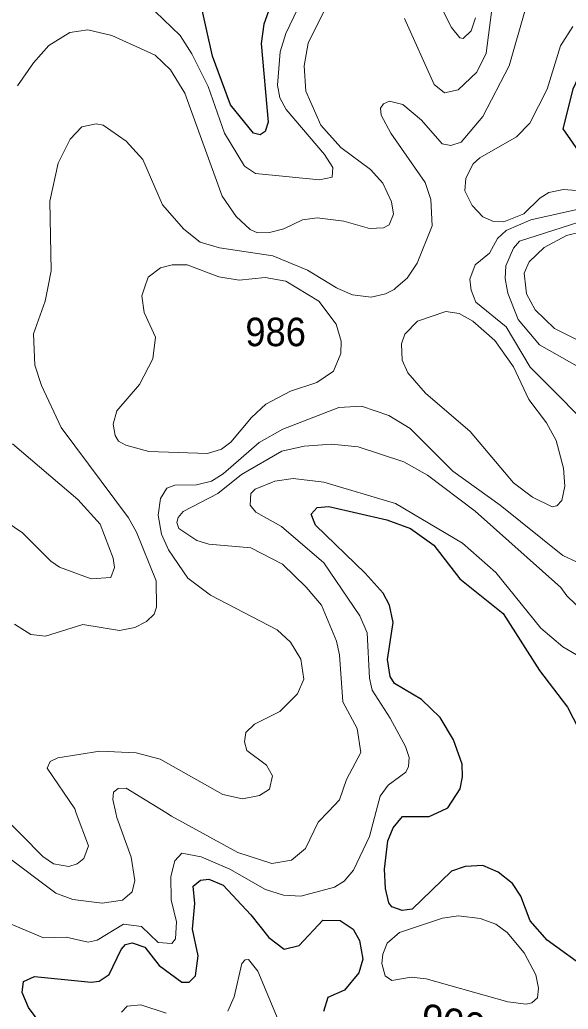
# Model space of a CAD drawing. Extents: x 473.9 to 500, y 7733.1 to 7760.8.
# Drawn here: x 478.365 to 479.903, y 7753.344 to 7756.121 of the extents above; entities that cross this region are included whole.
import ezdxf
from ezdxf.enums import TextEntityAlignment as Align

# ---------------------------------------------------------------- set-up
doc = ezdxf.new("R2010")
doc.units = 0
doc.header["$LTSCALE"] = 0.032
doc.layers.add('1', color=7, linetype='Continuous', lineweight=25)
doc.layers.add('2', color=7, linetype='Continuous', lineweight=13)
doc.layers.add('21', color=7, linetype='Continuous')
doc.layers.add('61', color=7, linetype='Continuous')

msp = doc.modelspace()

# ---------------------------------------------------------------- linework, layer by layer
at = {"layer": '1'}
for points in [[(479.0836, 7756.206), (479.0493, 7756.1087), (479.0414, 7756.0543), (479.0615, 7755.8337), (479.0529, 7755.8079), (479.0393, 7755.7982), (479.0201, 7755.8025), (478.9555, 7755.8829), (478.9053, 7756.0195), (478.8684, 7756.1871)], [(479.962, 7753.4517), (479.8435, 7753.5376), (479.7962, 7753.5923), (479.7701, 7753.6615), (479.7464, 7753.6963), (479.7067, 7753.7281), (479.6633, 7753.7472), (479.6133, 7753.7443), (479.5752, 7753.7312), (479.4652, 7753.6247), (479.4371, 7753.6212), (479.4086, 7753.6313), (479.3996, 7753.6421), (479.3903, 7753.6828), (479.3879, 7753.7371), (479.3974, 7753.8163), (479.4123, 7753.8529), (479.4382, 7753.8852), (479.513, 7753.8848), (479.5472, 7753.9005), (479.5656, 7753.9089), (479.5996, 7753.9629), (479.6064, 7753.9964), (479.6056, 7754.0315), (479.5815, 7754.1003), (479.5434, 7754.1631), (479.4915, 7754.2131), (479.4152, 7754.2582), (479.4038, 7754.2774), (479.396, 7754.3251), (479.4119, 7754.4292), (479.4014, 7754.4783), (479.3838, 7754.5116), (479.3335, 7754.5683), (479.1942, 7754.7022), (479.1822, 7754.7337), (479.1989, 7754.7518), (479.2312, 7754.7552), (479.394, 7754.7178), (479.4601, 7754.6932), (479.5258, 7754.6468), (479.5989, 7754.5524), (479.7203, 7754.4548), (479.8225, 7754.2946), (479.9008, 7754.1916), (479.9488, 7754.0995)], [(478.446, 7753.2733), (478.3895, 7753.3485), (478.3716, 7753.3909), (478.3758, 7753.4212), (478.4061, 7753.4359), (478.5649, 7753.4199), (478.5878, 7753.4223), (478.6154, 7753.4412), (478.6494, 7753.5119), (478.6611, 7753.5252), (478.68, 7753.5305), (478.716, 7753.5176), (478.7554, 7753.4661), (478.8197, 7753.4193), (478.8395, 7753.4196), (478.858, 7753.4373), (478.8651, 7753.494), (478.8492, 7753.5686), (478.8555, 7753.6404), (478.8508, 7753.6891), (478.8721, 7753.706), (478.8948, 7753.7092), (478.9348, 7753.6917), (479.0131, 7753.6086), (479.0632, 7753.545), (479.106, 7753.5128), (479.1482, 7753.5231), (479.2149, 7753.5934), (479.2635, 7753.5933), (479.2993, 7753.5685), (479.3179, 7753.5371), (479.3267, 7753.4845), (479.3154, 7753.4455), (479.2753, 7753.3976), (479.2291, 7753.3771), (479.2166, 7753.3378)]]:
    msp.add_lwpolyline(points, dxfattribs=at)
msp.add_lwpolyline([(480.2848, 7755.9407), (480.3121, 7756.0106), (480.3012, 7756.0601), (480.2751, 7756.0958), (480.2392, 7756.1082), (480.2076, 7756.1077), (480.1147, 7756.0738), (480.0119, 7756.0681), (479.9843, 7756.0523), (479.9665, 7756.0337), (479.9152, 7755.926), (479.888, 7755.815), (479.9437, 7755.7346), (479.9948, 7755.7134), (480.0536, 7755.7161), (480.0965, 7755.7676), (480.179, 7755.8326)], close=True, dxfattribs=at)
at = {"layer": '2'}
for points in [[(479.7154, 7756.3597), (479.6725, 7756.0273), (479.6464, 7755.974), (479.5937, 7755.925), (479.5561, 7755.9163), (479.5271, 7755.9392), (479.4433, 7756.1244)], [(479.265, 7756.2406), (479.1733, 7756.0553), (479.162, 7755.992), (479.1668, 7755.9209), (479.2094, 7755.8253), (479.265, 7755.7624), (479.3485, 7755.7008), (479.383, 7755.663), (479.4071, 7755.6098), (479.4129, 7755.5754), (479.4004, 7755.5457), (479.3844, 7755.5368), (479.3455, 7755.535), (479.2737, 7755.5556), (479.1992, 7755.5657), (479.1581, 7755.5592), (479.1052, 7755.5344), (479.0652, 7755.5237), (479.0314, 7755.5232), (479.0105, 7755.5324), (478.9715, 7755.5689), (478.9326, 7755.6265), (478.8282, 7755.9154), (478.7873, 7755.9805), (478.7444, 7756.0221), (478.6235, 7756.0772), (478.556, 7756.093), (478.5049, 7756.0857), (478.4464, 7756.0488)], [(478.745, 7756.1449), (478.8145, 7756.0773), (478.8477, 7756.0258), (478.8932, 7755.9336), (478.939, 7755.8034), (478.9947, 7755.7106), (479.0259, 7755.6893), (479.2056, 7755.6718), (479.2412, 7755.6792), (479.2428, 7755.7066), (479.2194, 7755.7432), (479.1115, 7755.869), (479.0939, 7755.9021), (479.088, 7755.9379), (479.0954, 7756.0311), (479.1105, 7756.0826), (479.1659, 7756.1987)], [(479.5198, 7756.2107), (479.5759, 7756.0993), (479.5984, 7756.0708), (479.6081, 7756.0683), (479.6308, 7756.0903), (479.6424, 7756.1263)], [(480.0945, 7754.8048), (480.0739, 7754.852), (480.0053, 7754.9354), (479.7956, 7755.146), (479.7287, 7755.2593), (479.6438, 7755.3283), (479.6302, 7755.3627), (479.6295, 7755.369), (479.6266, 7755.393), (479.642, 7755.433), (479.6821, 7755.466), (479.704, 7755.5069), (479.7287, 7755.5294), (479.7979, 7755.5599), (480.0027, 7755.6056), (480.0385, 7755.6234), (480.1332, 7755.691), (480.1863, 7755.7411), (480.3721, 7755.8613), (480.4187, 7755.9267), (480.4282, 7755.976), (480.4232, 7756.0221), (480.4067, 7756.0644), (480.3296, 7756.1867)], [(479.7829, 7756.1518), (479.7371, 7755.9923), (479.6632, 7755.8499), (479.6024, 7755.7773), (479.574, 7755.7683), (479.5497, 7755.7734), (479.4915, 7755.839), (479.4394, 7755.8832), (479.402, 7755.8925), (479.3849, 7755.8857), (479.3762, 7755.8731), (479.3786, 7755.8531), (479.4052, 7755.8027), (479.5013, 7755.6644), (479.5177, 7755.6163), (479.5215, 7755.5428), (479.4795, 7755.4378), (479.4512, 7755.3959), (479.4198, 7755.369), (479.4145, 7755.3645), (479.3905, 7755.3522), (479.3504, 7755.343), (479.2978, 7755.3494), (479.2566, 7755.3668), (479.253, 7755.369), (479.1713, 7755.4183), (479.0743, 7755.4587), (478.9249, 7755.4809), (478.8706, 7755.497), (478.8247, 7755.5339), (478.7649, 7755.6022), (478.71, 7755.7288), (478.6635, 7755.7804), (478.5991, 7755.8251), (478.5796, 7755.8293), (478.539, 7755.8205), (478.506, 7755.7865), (478.473, 7755.7187), (478.4496, 7755.6125), (478.4528, 7755.4169), (478.4434, 7755.369), (478.4361, 7755.3317), (478.4033, 7755.2396), (478.4076, 7755.1518), (478.4257, 7755.0948), (478.4807, 7754.9764), (478.6699, 7754.7232), (478.6926, 7754.683), (478.7472, 7754.5467), (478.7484, 7754.4725), (478.7414, 7754.4532), (478.7205, 7754.432), (478.6872, 7754.4156), (478.6445, 7754.4072), (478.542, 7754.4239), (478.4373, 7754.3906), (478.3959, 7754.3958), (478.3499, 7754.4248)], [(479.9158, 7756.1024), (479.8812, 7756.0482), (479.8433, 7755.926), (479.7948, 7755.8306), (479.7573, 7755.7929), (479.6553, 7755.7336), (479.6359, 7755.7164), (479.6156, 7755.6763), (479.6125, 7755.6412), (479.6331, 7755.5997), (479.6629, 7755.5681), (479.6931, 7755.5549), (479.7221, 7755.5541), (479.7782, 7755.5767), (479.8231, 7755.6205), (479.8486, 7755.6363), (479.889, 7755.6445), (479.963, 7755.6392)], [(478.4464, 7756.0488), (478.4037, 7756.0005), (478.3586, 7755.9357)], [(479.9344, 7755.1451), (479.8219, 7755.2086), (479.7621, 7755.2797), (479.7332, 7755.3537), (479.7304, 7755.369), (479.7256, 7755.3949), (479.7277, 7755.4304), (479.7491, 7755.4801), (479.7665, 7755.5001), (480.0751, 7755.599)], [(480.051, 7755.5529), (479.8981, 7755.516), (479.835, 7755.482), (479.7929, 7755.4422), (479.7795, 7755.4099), (479.7842, 7755.369), (479.7861, 7755.3522), (479.8098, 7755.3069), (479.8641, 7755.2547), (479.9314, 7755.2207)], [(478.3108, 7753.8929), (478.4292, 7753.7723), (478.4595, 7753.752), (478.5024, 7753.7447), (478.5262, 7753.7524), (478.5446, 7753.7673), (478.5574, 7753.8027), (478.5235, 7753.8942), (478.519, 7753.9064), (478.4418, 7754.0206), (478.4498, 7754.0395), (478.4719, 7754.0494), (478.5898, 7754.0685), (478.6916, 7754.0636), (478.7586, 7754.0455), (478.9339, 7753.9468), (478.9891, 7753.9344), (479.0368, 7753.9437), (479.0647, 7753.9617), (479.0735, 7753.9986), (479.0563, 7754.0287), (479.0014, 7754.07), (478.9948, 7754.094), (478.9991, 7754.1207), (479.0232, 7754.1437), (479.094, 7754.1792), (479.1438, 7754.229), (479.1618, 7754.2699), (479.1533, 7754.3261), (479.1237, 7754.3745), (479.0863, 7754.4086), (478.9001, 7754.5064), (478.8358, 7754.5538), (478.782, 7754.6333), (478.7624, 7754.6772), (478.7528, 7754.7308), (478.7597, 7754.7775), (478.7769, 7754.8065), (478.7997, 7754.8148), (478.8608, 7754.8162), (478.9028, 7754.8264), (478.9356, 7754.8465), (479.0361, 7754.9349), (479.1029, 7754.9724), (479.2593, 7755.0326), (479.3235, 7755.0366), (479.4002, 7755.0102), (479.4597, 7754.9735), (479.5788, 7754.8545), (479.7116, 7754.7589), (479.8874, 7754.6172), (479.9281, 7754.5985)], [(478.3443, 7754.9306), (478.5282, 7754.7746), (478.5905, 7754.7054), (478.627, 7754.6101), (478.6304, 7754.5839), (478.6205, 7754.5557), (478.5656, 7754.5519), (478.4767, 7754.5845), (478.452, 7754.6017), (478.3727, 7754.6808), (478.2345, 7754.7747)], [(478.3234, 7753.7769), (478.4659, 7753.6692), (478.5137, 7753.6516), (478.5962, 7753.6417), (478.653, 7753.6495), (478.6804, 7753.6729), (478.6875, 7753.7049), (478.6769, 7753.7709), (478.6372, 7753.8823), (478.6345, 7753.8949), (478.6263, 7753.9322), (478.6279, 7753.9534), (478.6411, 7753.9634), (478.6635, 7753.9642), (478.7746, 7753.8957), (478.7908, 7753.8858), (478.9762, 7753.7834), (479.0716, 7753.7528), (479.1272, 7753.7624), (479.1665, 7753.795), (479.2015, 7753.8685), (479.2302, 7753.8985), (479.2618, 7753.9316), (479.2814, 7753.9883), (479.3209, 7754.064), (479.3114, 7754.1321), (479.2708, 7754.2063), (479.2616, 7754.3385), (479.2526, 7754.3771), (479.2109, 7754.4778), (479.168, 7754.5288), (479.1013, 7754.5932), (479.0132, 7754.6394), (478.8953, 7754.6489), (478.861, 7754.66), (478.8107, 7754.6936), (478.8058, 7754.7099), (478.8092, 7754.7245), (478.8232, 7754.7408), (478.9199, 7754.7914), (478.9863, 7754.8447), (479.1001, 7754.9103), (479.1628, 7754.924), (479.2393, 7754.9304)], [(479.2393, 7754.9304), (479.3134, 7754.9222), (479.442, 7754.8799), (479.5084, 7754.8428), (479.6419, 7754.7415), (479.8818, 7754.528), (479.8989, 7754.5041), (479.973, 7754.4327)], [(479.6066, 7754.6524), (479.4184, 7754.7634), (479.2179, 7754.8234), (479.1316, 7754.834), (479.0802, 7754.8258), (479.0249, 7754.8037), (479.0128, 7754.7914), (479.0108, 7754.7589), (479.0273, 7754.7395), (479.0984, 7754.6989), (479.2174, 7754.5967), (479.3185, 7754.4478), (479.3389, 7754.4001), (479.3456, 7754.2732), (479.353, 7754.2392), (479.4039, 7754.161), (479.4463, 7754.0812), (479.4564, 7754.05), (479.4552, 7754.0254), (479.4474, 7754.009), (479.3979, 7753.973), (479.3756, 7753.9418), (479.3642, 7753.8994), (479.3452, 7753.8282), (479.3004, 7753.7339), (479.2743, 7753.7036), (479.2476, 7753.6862), (479.1526, 7753.661), (479.1043, 7753.664), (479.054, 7753.6799), (478.954, 7753.7368), (478.8734, 7753.7717), (478.8197, 7753.7823), (478.7999, 7753.76), (478.7884, 7753.7167), (478.7893, 7753.6507), (478.8042, 7753.5891), (478.8013, 7753.5417), (478.7917, 7753.5282), (478.7533, 7753.5311), (478.7066, 7753.5756), (478.6559, 7753.5826), (478.5816, 7753.5377), (478.5571, 7753.5316), (478.4949, 7753.5465), (478.4319, 7753.5444), (478.3407, 7753.5822)], [(479.9756, 7754.3097), (479.888, 7754.3615), (479.8255, 7754.4135), (479.6997, 7754.5694), (479.6066, 7754.6524)], [(479.0945, 7753.3024), (479.032, 7753.4511), (479.0066, 7753.4838), (478.9965, 7753.4829), (478.9879, 7753.4717), (478.9664, 7753.379), (478.9484, 7753.3383)], [(478.7753, 7753.3328), (478.7044, 7753.3562), (478.6665, 7753.3523), (478.6506, 7753.3351)]]:
    msp.add_lwpolyline(points, dxfattribs=at)
for points in [[(478.9567, 7754.9359), (479.0144, 7755.0048), (479.0553, 7755.0421), (479.1241, 7755.0784), (479.1978, 7755.1028), (479.2446, 7755.1347), (479.2656, 7755.1842), (479.2662, 7755.2191), (479.2522, 7755.2669), (479.2034, 7755.3311), (479.1418, 7755.369), (479.1113, 7755.3878), (479.0534, 7755.3976), (478.9799, 7755.3904), (478.923, 7755.3998), (478.8347, 7755.4338), (478.7924, 7755.4329), (478.7598, 7755.4245), (478.7254, 7755.3984), (478.7149, 7755.369), (478.7069, 7755.3466), (478.7138, 7755.2997), (478.7458, 7755.2299), (478.7382, 7755.1692), (478.7004, 7755.0973), (478.637, 7755.0232), (478.6273, 7754.9864), (478.6323, 7754.9539), (478.6421, 7754.9385), (478.6622, 7754.9267), (478.7264, 7754.9096), (478.8915, 7754.9041), (478.9302, 7754.9155)], [(479.7494, 7754.8213), (479.6274, 7754.9658), (479.5029, 7755.0735), (479.4531, 7755.1306), (479.4369, 7755.1658), (479.4351, 7755.2115), (479.4445, 7755.2389), (479.4799, 7755.2748), (479.5593, 7755.3021), (479.5974, 7755.2969), (479.6351, 7755.2751), (479.6972, 7755.221), (479.7494, 7755.1471), (479.7923, 7755.0554), (479.8414, 7754.9899), (479.8688, 7754.9405), (479.8894, 7754.8626), (479.8935, 7754.8117), (479.8851, 7754.7717), (479.8706, 7754.7568), (479.8578, 7754.7538), (479.8023, 7754.7812)], [(479.7793, 7753.5017), (479.7319, 7753.5596), (479.6993, 7753.5824), (479.6559, 7753.5988), (479.5952, 7753.6061), (479.5503, 7753.5994), (479.4299, 7753.5594), (479.3947, 7753.5288), (479.3825, 7753.4979), (479.3799, 7753.4718), (479.3897, 7753.438), (479.4082, 7753.4249), (479.4619, 7753.4334), (479.5042, 7753.4294), (479.7338, 7753.3649), (479.7845, 7753.3579), (479.8011, 7753.362), (479.8164, 7753.3759), (479.8196, 7753.4026), (479.8115, 7753.4406)]]:
    msp.add_lwpolyline(points, close=True, dxfattribs=at)

# ---------------------------------------------------------------- texts
at = {"layer": '21', "width": 0.95}
msp.add_text('986', height=0.08, dxfattribs=at).set_placement((478.9976, 7755.205))
at = {"layer": '61'}
msp.add_text('900', height=0.08, rotation=349.695, dxfattribs=at).set_placement((479.5723, 7753.2666), align=Align.CENTER)

doc.saveas('drawing.dxf')
